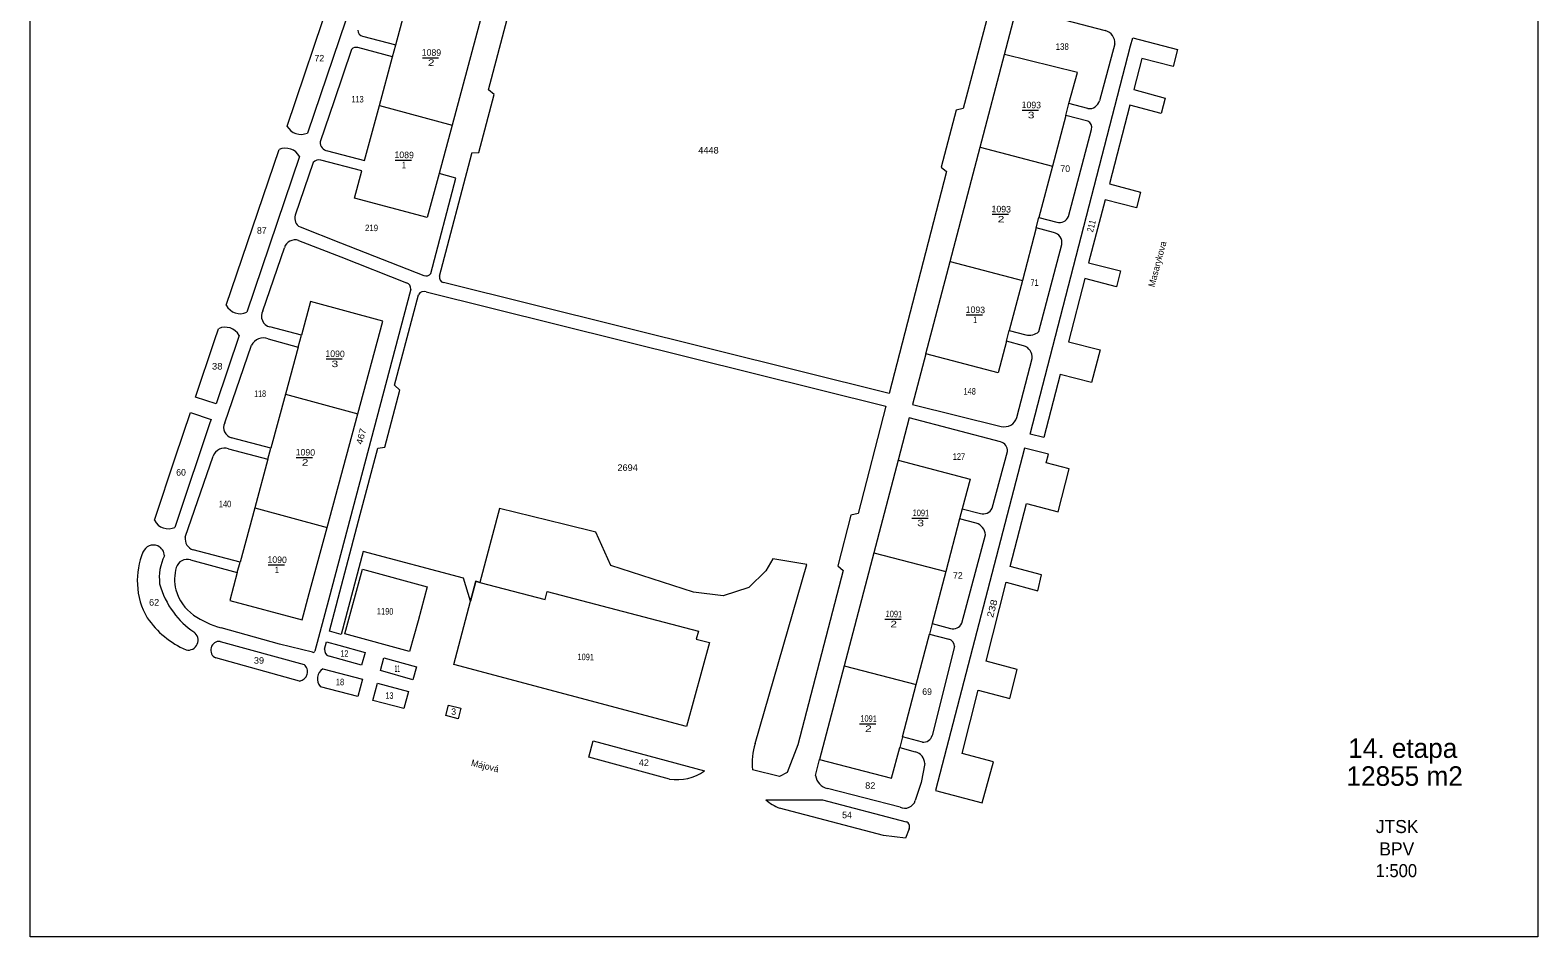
# Model space of a CAD drawing. Extents: x -843408 to -843177, y -1002968 to -1002716.
# Drawn here: x -843408.2 to -843176.9, y -1002968 to -1002829 of the extents above; entities that cross this region are included whole.
import ezdxf
from ezdxf.enums import TextEntityAlignment as Align

# ---------------------------------------------------------------- set-up
doc = ezdxf.new("R2010")
doc.units = 0
doc.header["$LTSCALE"] = 0.4
doc.layers.add('20', color=7, linetype='Continuous')
for name, color, linetype, lineweight in [('35', 7, 'Continuous', 13), ('38', 7, 'Continuous', 13), ('43', 7, 'Continuous', 13), ('44', 7, 'Continuous', 13)]:
    doc.layers.add(name, color=color, linetype=linetype, lineweight=lineweight)

msp = doc.modelspace()

# ---------------------------------------------------------------- linework, layer by layer
at = {"layer": '35'}
for p, q in [((-843348.003, -1002833.191), (-843345.503, -1002833.191)), ((-843255.987, -1002841.232), (-843253.487, -1002841.232)), ((-843352.181, -1002848.895), (-843349.681, -1002848.895)), ((-843260.598, -1002857.206), (-843258.098, -1002857.206)), ((-843264.566, -1002872.644), (-843262.066, -1002872.644)), ((-843362.78, -1002879.391), (-843360.28, -1002879.391)), ((-843367.336, -1002894.497), (-843364.836, -1002894.497)), ((-843272.922, -1002903.791), (-843270.422, -1002903.791)), ((-843371.665, -1002910.97), (-843369.165, -1002910.97)), ((-843277.067, -1002919.294), (-843274.567, -1002919.294)), ((-843280.944, -1002935.332), (-843278.444, -1002935.332))]:
    msp.add_line(p, q, dxfattribs=at)
at = {"layer": '38'}
for p, q in [((-843352.569, -1002833.043), (-843352.085, -1002831.243)), ((-843354.58, -1002840.52), (-843343.42, -1002843.52)), ((-843249.299, -1002842.032), (-843248.826, -1002840.235)), ((-843262.46, -1002846.91), (-843251.35, -1002849.83)), ((-843253.835, -1002859.296), (-843253.417, -1002857.703)), ((-843267.06, -1002864.43), (-843255.95, -1002867.35)), ((-843367.055, -1002877.574), (-843366.565, -1002875.763)), ((-843369.01, -1002884.8), (-843357.89, -1002887.8)), ((-843371.703, -1002894.766), (-843371.247, -1002893.078)), ((-843373.72, -1002902.23), (-843362.6, -1002905.23)), ((-843265.186, -1002902.384), (-843265.585, -1002903.904)), ((-843278.75, -1002909.1), (-843267.71, -1002912)), ((-843376.39, -1002912.116), (-843375.968, -1002910.553)), ((-843269.801, -1002919.98), (-843270.224, -1002921.597)), ((-843283.3, -1002926.44), (-843272.25, -1002929.33)), ((-843274.356, -1002937.359), (-843274.786, -1002938.998))]:
    msp.add_line(p, q, dxfattribs=at)
for points in [[(-843336.717, -1002818.592), (-843338.72, -1002826.01), (-843343.42, -1002843.52), (-843345.424, -1002850.965)], [(-843270.79, -1002878.58), (-843267.06, -1002864.43), (-843262.46, -1002846.91), (-843258.72, -1002832.69)], [(-843258.404, -1002876.684), (-843257.967, -1002875.024), (-843257.967, -1002875.024)], [(-843275.03, -1002894.93), (-843278.75, -1002909.1), (-843283.3, -1002926.44), (-843287.06, -1002940.8)]]:
    msp.add_lwpolyline(points, dxfattribs=at)
for points in [[(-843347.257, -1002914.344), (-843348.664, -1002919.526), (-843349.95, -1002924.26), (-843359.89, -1002921.56), (-843357.197, -1002911.644)], [(-843343.19, -1002926.25), (-843340.6, -1002916.51), (-843339.8, -1002913.49), (-843339.18, -1002913.65), (-843329.18, -1002916.27), (-843328.86, -1002915.05), (-843305.67, -1002921.13), (-843306, -1002922.35), (-843303.97, -1002922.88), (-843307.47, -1002935.74)]]:
    msp.add_lwpolyline(points, close=True, dxfattribs=at)
at = {"layer": '43'}
for p, q in [((-843358.786, -1002824.594), (-843365.612, -1002844.742)), ((-843352.569, -1002833.043), (-843357.88, -1002831.64)), ((-843241.77, -1002831.07), (-843244.131, -1002839.786)), ((-843248.9, -1002857.57), (-843245.36, -1002844.18)), ((-843378.08, -1002871.165), (-843369.989, -1002847.283)), ((-843366.835, -1002848.353), (-843374.926, -1002872.235)), ((-843364.743, -1002849.243), (-843367.49, -1002857.357)), ((-843253.417, -1002857.703), (-843250.672, -1002858.418)), ((-843253.45, -1002875.19), (-843249.91, -1002861.82)), ((-843372.45, -1002872.01), (-843369.173, -1002862.33)), ((-843257.967, -1002875.024), (-843255.442, -1002875.681)), ((-843378.314, -1002889.2), (-843374.216, -1002877.284)), ((-843256.79, -1002888.37), (-843254.44, -1002879.32)), ((-843371.247, -1002893.078), (-843377.282, -1002891.479)), ((-843260.61, -1002902.29), (-843258.26, -1002893.56)), ((-843384.36, -1002906.71), (-843380.071, -1002894.288)), ((-843263.06, -1002904.56), (-843265.585, -1002903.904)), ((-843265.27, -1002919.93), (-843261.64, -1002906.36)), ((-843375.968, -1002910.553), (-843383.136, -1002908.655)), ((-843362.412, -1002916.382), (-843364.488, -1002924.221)), ((-843379.002, -1002922.694), (-843366.156, -1002926.236)), ((-843362.991, -1002923.888), (-843362.695, -1002922.767)), ((-843266.36, -1002923.51), (-843269.81, -1002937.13)), ((-843366.859, -1002928.79), (-843379.707, -1002925.247)), ((-843363.246, -1002926.894), (-843357.189, -1002928.498)), ((-843271.31, -1002938.15), (-843274.356, -1002937.359)), ((-843310.07, -1002943.82), (-843322.48, -1002940.47)), ((-843274.72, -1002948.12), (-843285.85, -1002945.28))]:
    msp.add_line(p, q, dxfattribs=at)
for points in [[(-843345.387, -1002866.68), (-843340.42, -1002847.88), (-843340.395, -1002847.784), (-843339.341, -1002847.711), (-843336.998, -1002838.843), (-843337.84, -1002838.116), (-843334.981, -1002827.292), (-843329.565, -1002806.795)], [(-843357.162, -1002829.902), (-843352.085, -1002831.243), (-843349.87, -1002823.01), (-843347.869, -1002815.581)], [(-843368.765, -1002843.672), (-843361.94, -1002823.526), (-843358.786, -1002824.594)], [(-843258.72, -1002832.69), (-843256.83, -1002825.491), (-843243.25, -1002829.04)], [(-843261.48, -1002827.5), (-843265.045, -1002840.992), (-843266.14, -1002841.225)], [(-843358.878, -1002831.917), (-843361.554, -1002839.824), (-843363.681, -1002846.107)], [(-843362.542, -1002847.478), (-843356.857, -1002848.979), (-843354.58, -1002840.52), (-843352.569, -1002833.043)], [(-843245.93, -1002840.99), (-843248.826, -1002840.235), (-843247.517, -1002835.438), (-843258.72, -1002832.69)], [(-843266.14, -1002841.225), (-843268.447, -1002849.954), (-843267.597, -1002850.661), (-843276.399, -1002884.697), (-843344.764, -1002867.678)], [(-843245.907, -1002842.916), (-843249.299, -1002842.032), (-843251.35, -1002849.83), (-843253.417, -1002857.703)], [(-843345.424, -1002850.965), (-843347.24, -1002857.71), (-843358.4, -1002854.71), (-843357.283, -1002850.56), (-843363.565, -1002848.907)], [(-843346.72, -1002866.284), (-843342.855, -1002851.656), (-843345.424, -1002850.965)], [(-843366.76, -1002859.15), (-843360.57, -1002861.58), (-843347.776, -1002866.603)], [(-843251.17, -1002859.99), (-843253.835, -1002859.296), (-843255.95, -1002867.35), (-843257.967, -1002875.024)], [(-843366.99, -1002861.206), (-843360.51, -1002863.75), (-843350.414, -1002867.713)], [(-843349.778, -1002868.67), (-843362.412, -1002916.382), (-843364.488, -1002924.221)], [(-843362.6, -1002905.23), (-843357.89, -1002887.8), (-843354.04, -1002873.58), (-843365.16, -1002870.57), (-843366.565, -1002875.763), (-843371.42, -1002874.48)], [(-843353.757, -1002892.921), (-843351.441, -1002884.176), (-843352.276, -1002883.423), (-843351.2, -1002879.36), (-843348.598, -1002869.533)], [(-843347.407, -1002869.096), (-843276.903, -1002886.647), (-843281.177, -1002903.101), (-843282.277, -1002903.36), (-843284.298, -1002911.139), (-843283.44, -1002911.812), (-843290.39, -1002938.57), (-843292.04, -1002942.81), (-843293.23, -1002943.44), (-843297.371, -1002942.393)], [(-843382.786, -1002885.234), (-843379.885, -1002876.555), (-843379.282, -1002874.749)], [(-843376.113, -1002875.786), (-843379.624, -1002886.291), (-843382.786, -1002885.234)], [(-843371.655, -1002876.282), (-843367.055, -1002877.574), (-843369.01, -1002884.8), (-843371.247, -1002893.078)], [(-843255.77, -1002877.37), (-843258.404, -1002876.684), (-843259.671, -1002881.503)], [(-843259.671, -1002881.503), (-843270.79, -1002878.58), (-843272.806, -1002886.375), (-843259.21, -1002889.73)], [(-843389.104, -1002904.136), (-843385.85, -1002894.4), (-843383.579, -1002887.605), (-843380.417, -1002888.662)], [(-843380.417, -1002888.662), (-843380.586, -1002889.169), (-843385.59, -1002904.14), (-843385.948, -1002905.212)], [(-843259.299, -1002892.092), (-843273.339, -1002888.427), (-843275.03, -1002894.93)], [(-843377.73, -1002893.17), (-843371.703, -1002894.766), (-843373.72, -1002902.23), (-843375.968, -1002910.553)], [(-843296.94, -1002938.37), (-843289.02, -1002910.91), (-843294.26, -1002910.03), (-843295.34, -1002911.9), (-843297.93, -1002914.46), (-843301.84, -1002915.72), (-843306.39, -1002915.17), (-843319.09, -1002911.05), (-843321.41, -1002905.94), (-843326.13, -1002904.77), (-843336.15, -1002902.33), (-843339.18, -1002913.65), (-843339.8, -1002913.49), (-843340.6, -1002916.51), (-843341.67, -1002913.01), (-843357.09, -1002908.92), (-843357.09, -1002908.92), (-843360.47, -1002921.66), (-843362.266, -1002921.148), (-843357.523, -1002903.236), (-843354.836, -1002893.09), (-843353.757, -1002892.921)], [(-843275.03, -1002894.93), (-843263.99, -1002897.83), (-843265.186, -1002902.384), (-843262.39, -1002903.11)], [(-843383.55, -1002910.22), (-843376.39, -1002912.116), (-843377.55, -1002916.41), (-843366.45, -1002919.41), (-843365.352, -1002915.363), (-843362.6, -1002905.23)], [(-843265.585, -1002903.904), (-843267.71, -1002912), (-843269.801, -1002919.98), (-843266.99, -1002920.71)], [(-843383.55, -1002910.22), (-843376.39, -1002912.116), (-843377.55, -1002916.41), (-843366.45, -1002919.41)], [(-843364.83, -1002924.37), (-843369.93, -1002923.11), (-843378.88, -1002920.64)], [(-843364.83, -1002924.37), (-843369.93, -1002923.11), (-843378.88, -1002920.64)], [(-843274.356, -1002937.359), (-843272.25, -1002929.33), (-843270.224, -1002921.597), (-843267.25, -1002922.37)], [(-843362.695, -1002922.767), (-843360.799, -1002923.269), (-843356.789, -1002924.4), (-843357.34, -1002926.355), (-843362.322, -1002924.95)], [(-843357.189, -1002928.498), (-843357.89, -1002931.147), (-843363.63, -1002929.66)], [(-843322.48, -1002940.47), (-843321.8, -1002937.952), (-843304.734, -1002942.559)], [(-843287.707, -1002943.27), (-843287.06, -1002940.8), (-843276.02, -1002943.7), (-843274.786, -1002938.998), (-843272.39, -1002939.62)], [(-843270.95, -1002941.45), (-843271.47, -1002944.32), (-843272.39, -1002947.12)], [(-843295.32, -1002946.98), (-843286.63, -1002947.02), (-843273.8, -1002950.38)], [(-843273.35, -1002951.44), (-843273.9, -1002952.86), (-843277.29, -1002952.46), (-843293.21, -1002948.27)]]:
    msp.add_lwpolyline(points, dxfattribs=at)
for points in [[(-843251.282, -1002877.5), (-843239.36, -1002831.39), (-843239.01, -1002830.15), (-843232.17, -1002831.95), (-843232.84, -1002834.54), (-843237.63, -1002833.3), (-843238.88, -1002838.06), (-843234.06, -1002839.38), (-843234.69, -1002841.76), (-843239.47, -1002840.48), (-843242.62, -1002852.55), (-843237.83, -1002853.83), (-843238.44, -1002856.22), (-843243.26, -1002854.99), (-843245.82, -1002864.63), (-843240.93, -1002865.89), (-843241.52, -1002868.32), (-843246.36, -1002867.04), (-843248.88, -1002876.74), (-843244.01, -1002877.97), (-843245.34, -1002882.99), (-843250.17, -1002881.75), (-843252.67, -1002891.46), (-843254.78, -1002890.93)], [(-843260.41, -1002941.17), (-843265.21, -1002939.87), (-843262.74, -1002930.18), (-843257.9, -1002931.47), (-843256.75, -1002927.01), (-843261.54, -1002925.72), (-843258.44, -1002913.64), (-843253.58, -1002914.93), (-843253.01, -1002912.52), (-843257.82, -1002911.23), (-843255.33, -1002901.58), (-843250.49, -1002902.82), (-843248.8, -1002896.22), (-843252.31, -1002895.33), (-843251.95, -1002894.01), (-843255.662, -1002893.05), (-843269.28, -1002945.59), (-843262.13, -1002947.44)], [(-843353.896, -1002925.216), (-843348.899, -1002926.625), (-843349.45, -1002928.58), (-843354.448, -1002927.171)], [(-843354.895, -1002929.106), (-843350.12, -1002930.37), (-843350.85, -1002932.97), (-843355.578, -1002931.745)], [(-843343.978, -1002932.463), (-843342.104, -1002932.958), (-843342.526, -1002934.555), (-843344.4, -1002934.06)]]:
    msp.add_lwpolyline(points, close=True, dxfattribs=at)
for centre, radius, start, end in [((-843356.961, -1002829.0043), 0.9196, 177.86286, 257.4014), ((-843243.7519, -1002830.9604), 1.9849, 356.83602, 75.35287), ((-843358.1419, -1002832.6311), 1.0252, 75.20083, 135.87889), ((-843245.7212, -1002839.3554), 1.6479, 262.71975, 344.84599), ((-843246.4368, -1002843.8953), 1.1138, 345.19116, 61.5754), ((-843366.6149, -1002842.5162), 2.4412, 208.2454, 294.26336), ((-843368.9855, -1002849.5081), 2.4412, 28.2454, 114.26336), ((-843362.4, -1002846.2006), 1.2848, 175.84011, 263.65746), ((-843363.8843, -1002850.018), 1.1564, 73.94743, 137.94635), ((-843366.0885, -1002857.8318), 1.4794, 161.29789, 243.00458), ((-843250.2883, -1002856.945), 1.5225, 255.40196, 335.76086), ((-843367.5007, -1002862.8965), 1.7658, 73.17528, 161.29789), ((-843251.5153, -1002861.5765), 1.6237, 351.3754, 77.72133), ((-843347.45, -1002865.7728), 0.8915, 248.56658, 324.96932), ((-843350.7811, -1002868.6476), 1.0038, 358.70272, 68.56658), ((-843344.5597, -1002866.857), 0.8459, 167.92506, 256.03556), ((-843347.737, -1002870.0379), 0.9979, 70.70716, 149.59514), ((-843375.929, -1002870.0092), 2.4412, 208.24538, 294.26336), ((-843370.9896, -1002872.8508), 1.6851, 150.07095, 255.20171), ((-843378.2522, -1002876.9621), 2.4412, 28.79557, 114.94016), ((-843254.8992, -1002873.5978), 2.153, 255.40196, 312.30882), ((-843372.3506, -1002878.2781), 2.114, 70.79404, 151.95667), ((-843256.3071, -1002879.1649), 1.8735, 355.2504, 73.34159), ((-843376.8692, -1002889.9193), 1.6139, 153.51981, 255.16803), ((-843258.7242, -1002887.7614), 2.0276, 256.13656, 342.53398), ((-843378.3495, -1002894.8823), 1.821, 70.11096, 160.95034), ((-843259.6985, -1002893.4764), 1.4409, 356.6723, 73.90177), ((-843262.001, -1002901.6124), 1.5473, 255.43973, 334.02888), ((-843386.9507, -1002902.9865), 2.4412, 208.0959, 294.24049), ((-843263.6563, -1002906.4905), 2.0205, 3.70313, 72.8359), ((-843389.2647, -1002909.6355), 1.7078, 66.51429, 158.54861), ((-843389.2647, -1002909.6355), 1.7078, 1.86844, 66.51429), ((-843382.704, -1002907.0253), 1.6857, 169.21956, 255.16803), ((-843380.3437, -1002913.3782), 11.3817, 157.43666, 182.98039), ((-843380.8293, -1002912.9552), 7.5277, 153.36, 187.05705), ((-843384.0993, -1002911.8528), 1.7227, 71.40668, 163.37806), ((-843384.0993, -1002911.8528), 1.7227, 71.40668, 163.37806), ((-843379.709, -1002913.1634), 6.3045, 163.37806, 194.95162), ((-843379.709, -1002913.1634), 6.3045, 163.37806, 194.95162), ((-843381.1176, -1002913.6074), 10.5986, 181.96081, 211.02496), ((-843375.6951, -1002910.4705), 13.0579, 195.13578, 216.51307), ((-843379.1431, -1002913.0123), 6.8902, 194.95162, 235.05229), ((-843379.1431, -1002913.0123), 6.8902, 194.95162, 235.05229), ((-843378.7874, -1002911.3662), 13.7694, 214.02022, 246.67189), ((-843375.6951, -1002910.4705), 13.0579, 216.51307, 235.71895), ((-843375.2294, -1002907.412), 13.7225, 235.05229, 254.57168), ((-843375.2294, -1002907.412), 13.7225, 235.05229, 254.57168), ((-843383.93, -1002922.5117), 1.53, 258.30886, 54.89224), ((-843266.6124, -1002919.2562), 1.502, 255.43973, 333.34776), ((-843379.1126, -1002924.037), 1.3479, 85.30084, 243.84252), ((-843364.7425, -1002924.1036), 0.2804, 251.81431, 335.22612), ((-843364.7425, -1002924.1036), 0.2804, 251.81431, 335.22612), ((-843362.0675, -1002924.0475), 0.9375, 170.18143, 254.2502), ((-843267.5489, -1002923.5208), 1.1889, 0.51872, 75.43972), ((-843367.0662, -1002927.3591), 1.4456, 278.236, 50.96694), ((-843362.2767, -1002928.4384), 1.8231, 122.11218, 222.07213), ((-843271.135, -1002936.7944), 1.3669, 262.64568, 345.78573), ((-843287.4542, -1002941.4198), 9.9641, 162.17696, 185.60623), ((-843272.8737, -1002941.4822), 1.924, 0.95765, 75.43972), ((-843308.9691, -1002936.5592), 7.3438, 261.37862, 305.21888), ((-843285.2282, -1002942.843), 2.5151, 189.77561, 255.68551), ((-843290.5876, -1002941.6101), 7.1576, 228.61114, 248.50777), ((-843273.9961, -1002946.5923), 1.6905, 244.64557, 341.81096), ((-843273.9843, -1002951.0838), 0.7275, 330.68059, 75.3246)]:
    msp.add_arc(centre, radius, start, end, dxfattribs=at)
at = {"layer": '44'}
msp.add_lwpolyline([(-843176.897, -1002715.941), (-843176.897, -1002968.008), (-843408.163, -1002968.008), (-843408.163, -1002715.941)], close=True, dxfattribs=at)

# ---------------------------------------------------------------- texts
at = {"layer": '20'}
for s, rotation, p in [('Masarykova', 74.973, (-843235.721, -1002868.453)), ('Májová', 346.137, (-843340.598, -1002941.758))]:
    msp.add_text(s, height=1, rotation=rotation, dxfattribs=at).set_placement(p)
at = {"layer": '35'}
for s, p in [('1089', (-843346.6225, -1002832.8944)), ('1093', (-843254.605, -1002840.9352)), ('1089', (-843350.801, -1002848.5974)), ('1093', (-843259.2175, -1002856.9092)), ('1093', (-843263.1855, -1002872.3472)), ('1090', (-843361.4, -1002879.0934)), ('1090', (-843365.9555, -1002894.2004)), ('1090', (-843370.2835, -1002910.6734))]:
    msp.add_text(s, height=1, rotation=358.734, dxfattribs=at).set_placement(p, align=Align.CENTER)
for s, width, p in [('2', 1.35, (-843346.657, -1002834.4443)), ('3', 1.4, (-843254.6405, -1002842.4845)), ('1', 0.7, (-843350.8355, -1002850.1468)), ('2', 1.35, (-843259.251, -1002858.4583)), ('1', 0.7, (-843263.2205, -1002873.8968)), ('3', 1.4, (-843361.4335, -1002880.6435)), ('2', 1.35, (-843365.989, -1002895.7493)), ('1091', 0.85, (-843271.541, -1002903.4946)), ('3', 1.4, (-843271.5765, -1002905.0435)), ('1', 0.7, (-843370.318, -1002912.2229)), ('1190', 0.85, (-843353.7205, -1002918.5875)), ('1091', 0.85, (-843275.686, -1002918.9976)), ('2', 1.35, (-843275.72, -1002920.5463)), ('1091', 0.85, (-843322.95, -1002925.5886)), ('1091', 0.85, (-843279.5635, -1002935.0345)), ('2', 1.35, (-843279.597, -1002936.5843))]:
    msp.add_text(s, height=1, rotation=358.734, dxfattribs=dict(at, width=width)).set_placement(p, align=Align.CENTER)
at = {"layer": '43'}
for s, width, p in [('138', 0.9, (-843250.852, -1002831.987)), ('113', 0.7, (-843358.873, -1002840.06)), ('4448', 1.05, (-843305.678, -1002847.887)), ('219', 0.9, (-843356.803, -1002859.791)), ('71', 0.7, (-843254.724, -1002868.18)), ('38', 1.1, (-843380.284, -1002881.012)), ('118', 0.65, (-843373.798, -1002885.218)), ('148', 0.85, (-843264.998, -1002884.859)), ('127', 0.85, (-843266.644, -1002894.861)), ('2694', 1.05, (-843318.081, -1002896.555)), ('140', 0.85, (-843379.215, -1002902.131)), ('62', 1.05, (-843389.929, -1002917.214)), ('12', 0.8, (-843360.572, -1002925.056)), ('39', 1.05, (-843373.847, -1002926.122)), ('11', 0.45, (-843352.264, -1002927.374)), ('18', 0.75, (-843361.271, -1002929.43)), ('13', 0.8, (-843353.661, -1002931.509)), ('42', 1.05, (-843314.806, -1002941.8)), ('82', 1.05, (-843280.074, -1002945.307))]:
    msp.add_text(s, height=1, dxfattribs=dict(at, width=width)).set_placement(p)
for s, p in [('72', (-843364.548, -1002833.765)), ('70', (-843250.136, -1002850.708)), ('87', (-843373.374, -1002860.188)), ('60', (-843385.762, -1002897.281)), ('72', (-843266.603, -1002913.086)), ('69', (-843271.327, -1002930.907)), ('3', (-843343.569, -1002933.967)), ('54', (-843283.612, -1002949.826))]:
    msp.add_text(s, height=1, dxfattribs=at).set_placement(p)
for s, rotation, width, p in [('211', 75.504, 0.8, (-843245.141, -1002860.014)), ('467', 74.878, 1.1, (-843357.229, -1002892.583)), ('238', 75.469, 1.25, (-843260.465, -1002919.132))]:
    msp.add_text(s, height=1, rotation=rotation, dxfattribs=dict(at, width=width)).set_placement(p)
at = {"layer": '44'}
for s, height, p in [('14. etapa', 3, (-843205.985, -1002940.569)), ('12855 m2', 3, (-843206.249, -1002944.849)), ('JTSK', 2, (-843201.749, -1002952.093)), ('BPV', 2, (-843201.209, -1002955.522))]:
    msp.add_text(s, height=height, dxfattribs=at).set_placement(p)
at = {"layer": '44', "width": 0.95}
msp.add_text('1:500', height=2, dxfattribs=at).set_placement((-843201.78, -1002958.856))

doc.saveas('drawing.dxf')
